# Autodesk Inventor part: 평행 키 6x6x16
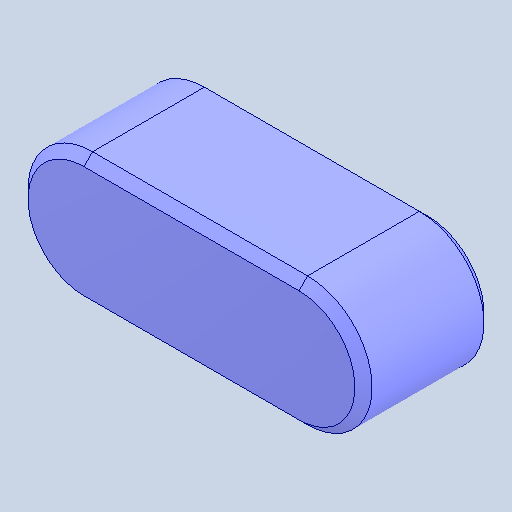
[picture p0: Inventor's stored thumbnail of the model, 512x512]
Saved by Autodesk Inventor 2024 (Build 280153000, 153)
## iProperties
Created: 2025-11
Part Number: 평행 키 6x6x16
Material: 강철, 연강
Description: 키 및 해당 키홈
Document SubType Name: Modeling
Designer: Eud07
Density: 7.85 g/cm^3
Appearance: 기본값
Author: jhkim
Sending System: Autodesk Inventor 2026
Preprocessor: ST-DEVELOPER v20.1
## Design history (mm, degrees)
node "평행 키 6x6x161"
node "솔리드1"
body "Solid1"
